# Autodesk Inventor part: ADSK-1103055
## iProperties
Shininess: 50.0
Length Units: 11272
Angle Units: 11279
Time Units: 11290
Mass Units: 11286
Length Display Precision: 4
Angle Display Precision: 2
Compacted: True
Created: 2000-08
Part Number: ADSK-1103055
Document SubType Name: Modeling
Mass: 8.22663 g
Surface Area: 26.2406 cm^2
Volume: 3.03566 cm^3
Density: 2.71 g/cm^3
Material: Aluminum-6061
Density: 0.0
Volumn: 0.0
Area: 0.0
PropertySet Name: Model Information
Control State: 0
Master: False
Checked Out: False
Author: Autodesk, Inc.
